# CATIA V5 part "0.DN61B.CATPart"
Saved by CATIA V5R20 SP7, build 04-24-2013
Part number: 0.DN61B
Material "Nessuno"
Bounding box of the stored display mesh (mm): x 0 to 149.213, y -135.185 to 0, z -56.919 to 41.584
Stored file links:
  C:\Users\designer2\Desktop\Ottobre 2022\25-10-2022\04\Yori Evo 48V\0.DN61B.CATPart
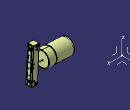
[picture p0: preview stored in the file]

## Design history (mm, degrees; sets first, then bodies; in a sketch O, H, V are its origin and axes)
AxisSystem1: origin (0, 0, 0), X (1, 0, 0), Y (0, 1, 0), Z (0, 0, 1)
Set1
  DatumSurface1
Body1 (main body), material "Nessuno"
